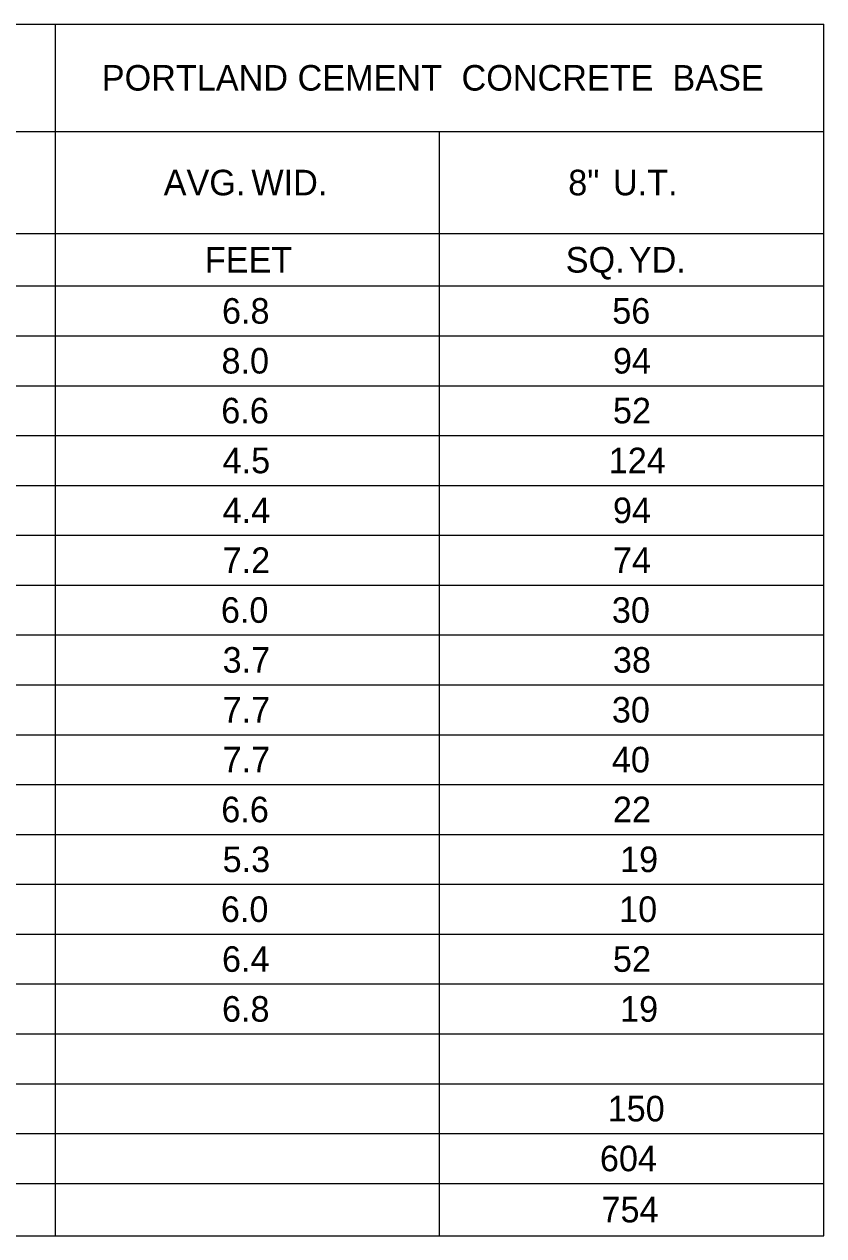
# Model space of a CAD drawing. Extents: x 1226567 to 1228151, y 151309 to 152305.
# Drawn here: x 1227800.4 to 1227956.7, y 151363.7 to 151600.6 of the extents above; entities that cross this region are included whole.
import ezdxf

# ---------------------------------------------------------------- set-up
doc = ezdxf.new("R2010")
doc.units = 0
doc.layers.add('R_Dimension', color=7, linetype='Continuous')

msp = doc.modelspace()

# ---------------------------------------------------------------- linework, layer by layer
at = {"layer": 'R_Dimension'}
for p, q in [((1226721.38, 151600.64), (1227956.7, 151600.64)), ((1227806.55, 151363.71), (1227806.55, 151600.64)), ((1227956.7, 151363.71), (1227956.7, 151600.64)), ((1227009.98, 151579.68), (1227956.7, 151579.68)), ((1227881.63, 151363.71), (1227881.63, 151579.68)), ((1227656.4, 151559.69), (1227956.7, 151559.69)), ((1227457.5, 151549.45), (1227956.7, 151549.45)), ((1226721.38, 151539.7), (1227956.7, 151539.7)), ((1226721.38, 151529.95), (1227956.7, 151529.95)), ((1226721.38, 151520.2), (1227956.7, 151520.2)), ((1226721.38, 151510.45), (1227956.7, 151510.45)), ((1226721.38, 151500.7), (1227956.7, 151500.7)), ((1226721.38, 151490.95), (1227956.7, 151490.95)), ((1226721.38, 151481.2), (1227956.7, 151481.2)), ((1226721.38, 151471.45), (1227956.7, 151471.45)), ((1226721.38, 151461.7), (1227956.7, 151461.7)), ((1226721.38, 151451.95), (1227956.7, 151451.95)), ((1226721.38, 151442.2), (1227956.7, 151442.2)), ((1226721.38, 151432.45), (1227956.7, 151432.45)), ((1226721.38, 151422.7), (1227956.7, 151422.7)), ((1226721.38, 151412.95), (1227956.7, 151412.95)), ((1226721.38, 151403.2), (1227956.7, 151403.2)), ((1226721.38, 151393.45), (1227956.7, 151393.45)), ((1226721.38, 151383.7), (1227956.7, 151383.7)), ((1226721.38, 151373.95), (1227956.7, 151373.95)), ((1226721.38, 151363.71), (1227956.7, 151363.71))]:
    msp.add_line(p, q, dxfattribs=at)

# ---------------------------------------------------------------- texts
for s, p in [('PORTLAND', (1227815.59, 151587.66)), (' CEMENT', (1227852, 151587.66)), (' CONCRETE', (1227884.05, 151587.66)), (' BASE', (1227925.27, 151587.66)), ('AVG.', (1227827.69, 151567.18)), (' WID.', (1227842.97, 151567.18)), ('8"', (1227906.76, 151567.18)), (' U.T.', (1227913.65, 151567.18)), ('FEET', (1227835.73, 151552.07)), ('SQ.', (1227906.27, 151552.07)), (' YD.', (1227916.75, 151552.07)), ('6.8', (1227839.09, 151542.08)), ('56', (1227915.37, 151542.08)), ('8.0', (1227838.99, 151532.33)), ('94', (1227915.5, 151532.33)), ('6.6', (1227838.95, 151522.58)), ('52', (1227915.5, 151522.58)), ('4.5', (1227839.21, 151512.83)), ('124', (1227914.68, 151512.83)), ('4.4', (1227839.21, 151503.08)), ('94', (1227915.5, 151503.08)), ('7.2', (1227839.21, 151493.33)), ('74', (1227915.5, 151493.33)), ('6.0', (1227838.87, 151483.58)), ('30', (1227915.29, 151483.58)), ('3.7', (1227839.21, 151473.83)), ('38', (1227915.5, 151473.83)), ('7.7', (1227839.21, 151464.08)), ('30', (1227915.29, 151464.08)), ('7.7', (1227839.21, 151454.33)), ('40', (1227915.29, 151454.33)), ('6.6', (1227838.95, 151444.58)), ('22', (1227915.5, 151444.58)), ('5.3', (1227839.21, 151434.83)), ('19', (1227916.9, 151434.83)), ('6.0', (1227838.87, 151425.08)), ('10', (1227916.71, 151425.08)), ('6.4', (1227839.09, 151415.33)), ('52', (1227915.5, 151415.33)), ('6.8', (1227839.09, 151405.58)), ('19', (1227916.9, 151405.58)), ('150', (1227914.46, 151386.08)), ('604', (1227912.95, 151376.33)), ('754', (1227913.26, 151366.33))]:
    msp.add_text(s, height=5, dxfattribs=at).set_placement(p)

doc.saveas('drawing.dxf')
